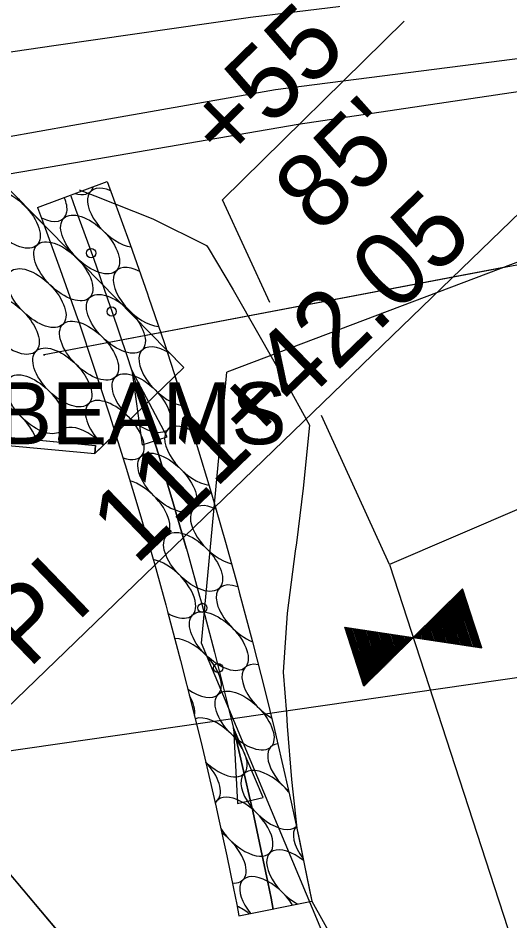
# Model space of a CAD drawing. Extents: x 1660112 to 1662239, y 668919 to 671377.
# Drawn here: x 1661383 to 1661422.7, y 670205.1 to 670278 of the extents above; entities that cross this region are included whole.
import ezdxf

# ---------------------------------------------------------------- set-up
doc = ezdxf.new("R2010")
doc.units = 0
for name, color, linetype in [('R_Concrete', 7, 'Continuous'), ('R_Horz Alg', 7, 'Continuous'), ('R_Horz Alg Annot', 7, 'Continuous'), ('R_Proposed Const Limits_Cut', 7, 'Continuous'), ('R_Proposed Const Limits_Hand', 7, 'Continuous'), ('R_ROW', 7, 'Continuous'), ('R_ROW Annot', 7, 'Continuous'), ('R_Water', 7, 'Continuous'), ('R_Water Annot', 7, 'Continuous'), ('S_BASELINE', 7, 'Continuous'), ('S_FENCE', 7, 'Continuous'), ('S_MSC_PT_SYM', 7, 'Continuous'), ('S_STREAM', 7, 'Continuous'), ('S_SURVEY_TEXT_ANNOT', 7, 'Continuous')]:
    doc.layers.add(name, color=color, linetype=linetype)

msp = doc.modelspace()

# ---------------------------------------------------------------- linework, layer by layer
at = {"layer": 'R_Concrete'}
for p, q in [((1661360.775, 670246.186), (1661389.245, 670243.511)), ((1661360.775, 670246.186), (1661389.245, 670243.511)), ((1661360.725, 670245.521), (1661389.183, 670242.848)), ((1661360.725, 670245.521), (1661389.183, 670242.848)), ((1661389.183, 670242.848), (1661389.245, 670243.511)), ((1661389.183, 670242.848), (1661389.245, 670243.511))]:
    msp.add_line(p, q, dxfattribs=at)
at = {"layer": 'R_Horz Alg'}
msp.add_arc((1655846.994, 664877.91), 7639.437, 42.561815, 45.4300379, dxfattribs=at)
at = {"layer": 'R_Horz Alg Annot'}
msp.add_lwpolyline([(1661344.445, 670185.981), (1661430.771, 670269.334)], dxfattribs=at)
at = {"layer": 'R_Proposed Const Limits_Cut'}
msp.add_line((1661397.789, 670227.54), (1661399.846, 670249.439), dxfattribs=at)
for points in [[(1661343.395, 670328.65), (1661484.178, 670303.544), (1661489.924, 670283.525), (1661399.846, 670249.439)], [(1661407.912, 670131.742), (1661429.38, 670152.079), (1661397.789, 670227.54)]]:
    msp.add_lwpolyline(points, dxfattribs=at)
at = {"layer": 'R_Proposed Const Limits_Hand'}
msp.add_line((1661406.708, 670206.706), (1661451.037, 670128.131), dxfattribs=at)
msp.add_lwpolyline([(1661387.926, 670264.146), (1661389.193, 670263.651), (1661393.882, 670261.815), (1661398.201, 670259.66), (1661398.328, 670259.454), (1661400.352, 670256.071), (1661402.442, 670252.447), (1661404.421, 670248.948), (1661404.5, 670248.807), (1661406.524, 670245.15), (1661406.004, 670240.056), (1661405.464, 670235.662), (1661405.378, 670234.982), (1661404.709, 670229.965), (1661404.396, 670225.211), (1661404.659, 670221.857), (1661404.731, 670220.85), (1661405.08, 670216.54), (1661405.188, 670215.557), (1661405.492, 670212.599), (1661406.708, 670206.706)], dxfattribs=at)
at = {"layer": 'R_ROW'}
msp.add_lwpolyline([(1661492.291, 670317.34), (1661506.22, 670273.906), (1661412.985, 670233.905), (1661445.828, 670132.902)], dxfattribs=at)
at = {"layer": 'R_ROW Annot'}
for points in [[(1661403.306, 670255.05), (1661399.509, 670263.348), (1661414.156, 670277.771)], [(1661412.985, 670233.905), (1661407.48, 670245.931)]]:
    msp.add_lwpolyline(points, dxfattribs=at)
at = {"layer": 'R_Water'}
for p, q in [((1661384.57, 670262.73), (1661390.195, 670264.818)), ((1661384.57, 670262.73), (1661390.195, 670264.818)), ((1661392.168, 670249.581), (1661393.019, 670243.548)), ((1661395.031, 670244.203), (1661392.168, 670249.581)), ((1661393.019, 670243.548), (1661395.031, 670244.203)), ((1661400.398, 670220.7), (1661400.71, 670214.616)), ((1661402.773, 670215.09), (1661400.398, 670220.7)), ((1661400.71, 670214.616), (1661402.773, 670215.09)), ((1661400.822, 670205.542), (1661406.708, 670206.706)), ((1661400.822, 670205.542), (1661406.708, 670206.706))]:
    msp.add_line(p, q, dxfattribs=at)
for points in [[(1661390.195, 670264.818), (1661390.6, 670263.727), (1661392.05, 670259.735), (1661393.45, 670255.742), (1661393.534, 670255.496), (1661394.807, 670251.73), (1661396.112, 670247.724), (1661397.319, 670243.877), (1661397.372, 670243.707), (1661398.578, 670239.704), (1661399.739, 670235.694), (1661400.703, 670232.227), (1661400.854, 670231.673), (1661401.917, 670227.668), (1661402.934, 670223.658), (1661403.683, 670220.576), (1661403.906, 670219.638), (1661404.826, 670215.641), (1661405.036, 670214.699), (1661405.703, 670211.626), (1661406.263, 670208.93), (1661406.528, 670207.614), (1661406.708, 670206.706)], [(1661390.195, 670264.818), (1661390.6, 670263.727), (1661392.05, 670259.735), (1661393.45, 670255.742), (1661393.534, 670255.496), (1661394.807, 670251.73), (1661396.112, 670247.724), (1661397.319, 670243.877), (1661397.372, 670243.707), (1661398.578, 670239.704), (1661399.739, 670235.694), (1661400.703, 670232.227), (1661400.854, 670231.673), (1661401.917, 670227.668), (1661402.934, 670223.658), (1661403.683, 670220.576), (1661403.906, 670219.638), (1661404.826, 670215.641), (1661405.036, 670214.699), (1661405.703, 670211.626), (1661406.263, 670208.93), (1661406.528, 670207.614), (1661406.708, 670206.706)], [(1661387.236, 670263.673), (1661387.637, 670262.592), (1661389.075, 670258.628), (1661390.465, 670254.66), (1661390.544, 670254.431), (1661391.807, 670250.69), (1661393.101, 670246.716), (1661394.299, 670242.893), (1661394.346, 670242.74), (1661395.544, 670238.763), (1661396.693, 670234.785), (1661397.65, 670231.342), (1661397.795, 670230.806), (1661398.85, 670226.827), (1661399.858, 670222.849), (1661400.6, 670219.791), (1661400.818, 670218.871), (1661401.732, 670214.895), (1661401.937, 670213.972), (1661402.598, 670210.921), (1661403.153, 670208.249), (1661403.414, 670206.948), (1661403.592, 670206.045)], [(1661384.57, 670262.73), (1661384.968, 670261.658), (1661386.399, 670257.719), (1661387.782, 670253.773), (1661387.855, 670253.56), (1661389.112, 670249.841), (1661390.397, 670245.897), (1661391.59, 670242.096), (1661391.632, 670241.959), (1661392.824, 670238.005), (1661393.966, 670234.056), (1661394.918, 670230.635), (1661395.059, 670230.116), (1661396.109, 670226.161), (1661397.111, 670222.211), (1661397.849, 670219.174), (1661398.063, 670218.273), (1661398.974, 670214.315), (1661399.176, 670213.41), (1661399.834, 670210.379), (1661400.385, 670207.728), (1661400.644, 670206.44), (1661400.822, 670205.542)], [(1661384.57, 670262.73), (1661384.968, 670261.658), (1661386.399, 670257.719), (1661387.782, 670253.773), (1661387.855, 670253.56), (1661389.112, 670249.841), (1661390.397, 670245.897), (1661391.59, 670242.096), (1661391.632, 670241.959), (1661392.824, 670238.005), (1661393.966, 670234.056), (1661394.918, 670230.635), (1661395.059, 670230.116), (1661396.109, 670226.161), (1661397.111, 670222.211), (1661397.849, 670219.174), (1661398.063, 670218.273), (1661398.974, 670214.315), (1661399.176, 670213.41), (1661399.834, 670210.379), (1661400.385, 670207.728), (1661400.644, 670206.44), (1661400.822, 670205.542)], [(1661396.562, 670235.24), (1661395.544, 670238.763), (1661394.346, 670242.74), (1661394.299, 670242.893), (1661393.101, 670246.716), (1661392.168, 670249.581)], [(1661395.658, 670249.116), (1661396.112, 670247.724), (1661397.319, 670243.877), (1661397.372, 670243.707), (1661398.578, 670239.704), (1661399.739, 670235.694), (1661400.703, 670232.227), (1661400.854, 670231.673), (1661401.917, 670227.668), (1661402.934, 670223.658), (1661403.683, 670220.576), (1661403.906, 670219.638), (1661404.826, 670215.641), (1661405.036, 670214.699), (1661405.703, 670211.626), (1661406.263, 670208.93), (1661406.528, 670207.614), (1661406.708, 670206.706)], [(1661396.572, 670235.204), (1661396.562, 670235.24)], [(1661403.592, 670206.045), (1661403.414, 670206.948), (1661403.153, 670208.249), (1661402.598, 670210.921), (1661401.937, 670213.972), (1661401.732, 670214.895), (1661400.818, 670218.871), (1661400.6, 670219.791), (1661400.38, 670220.696)]]:
    msp.add_lwpolyline(points, dxfattribs=at)
for centre in [(1661388.886, 670259.043), (1661390.545, 670254.317), (1661397.868, 670230.391), (1661399.138, 670225.545)]:
    msp.add_circle(centre, 0.375, dxfattribs=at)
at = {"layer": 'R_Water Annot'}
msp.add_lwpolyline([(1661324.141, 670309.192), (1661324.685, 670308.806), (1661313.922, 670293.642), (1661360.775, 670246.186), (1661389.245, 670243.511), (1661389.183, 670242.848), (1661396.368, 670249.803), (1661331.242, 670316.233)], close=True, dxfattribs=at)
for points in [[(1661385.099, 670261.298), (1661331.242, 670316.233), (1661324.141, 670309.192), (1661324.685, 670308.806), (1661313.922, 670293.642), (1661360.775, 670246.186), (1661389.245, 670243.511), (1661389.183, 670242.848), (1661390.848, 670244.46)], [(1661385.099, 670261.298), (1661331.242, 670316.233), (1661324.141, 670309.192), (1661324.685, 670308.806), (1661313.922, 670293.642), (1661360.775, 670246.186), (1661389.245, 670243.511), (1661389.183, 670242.848), (1661390.848, 670244.46)], [(1661395.658, 670249.116), (1661396.368, 670249.803), (1661394.97, 670251.228)]]:
    msp.add_lwpolyline(points, dxfattribs=at)
for centre in [(1661382.4, 670261.815), (1661382.4, 670261.815), (1661388.807, 670259.736), (1661388.807, 670259.736), (1661386.643, 670257.572), (1661386.643, 670257.572), (1661384.479, 670255.408), (1661384.479, 670255.408), (1661382.315, 670253.244), (1661382.315, 670253.244), (1661390.886, 670253.329), (1661390.886, 670253.329), (1661388.722, 670251.165), (1661388.722, 670251.165), (1661386.558, 670249.002), (1661386.558, 670249.002), (1661384.394, 670246.838), (1661384.394, 670246.838), (1661392.964, 670246.923), (1661392.964, 670246.923), (1661395.043, 670240.516), (1661395.043, 670240.516), (1661397.122, 670234.11), (1661397.122, 670234.11), (1661399.201, 670227.704), (1661399.201, 670227.704), (1661401.28, 670221.297), (1661401.28, 670221.297)]:
    msp.add_ellipse(centre, major_axis=(2.121, -2.121), ratio=0.51, dxfattribs=at)
for centre, start_param, end_param in [((1661386.728, 670266.142), 5.546257, 6.460002), ((1661386.728, 670266.142), 5.546257, 6.460002), ((1661390.97, 670261.899), 2.254283, 5.687545), ((1661390.97, 670261.899), 2.254283, 5.687545), ((1661386.728, 670266.142), 0.176817, 0.27749), ((1661386.728, 670266.142), 0.176817, 0.27749), ((1661384.564, 670263.978), 4.477364, 4.908534), ((1661384.564, 670263.978), 4.477364, 4.908534), ((1661384.564, 670263.978), 0.351911, 0.90907), ((1661384.564, 670263.978), 0.351911, 0.90907), ((1661384.564, 670263.978), 5.31948, 6.635096), ((1661384.564, 670263.978), 5.31948, 6.635096), ((1661393.049, 670255.493), 2.140255, 5.756238), ((1661393.049, 670255.493), 2.140255, 5.756238), ((1661395.128, 670249.087), 1.988124, 5.76284), ((1661395.128, 670249.087), 1.988124, 5.76284), ((1661382.231, 670244.674), 0.793691, 4.385656), ((1661382.231, 670244.674), 0.793691, 4.385656), ((1661390.801, 670244.759), 0.182712, 4.786912), ((1661390.801, 670244.759), 0.182712, 4.786912), ((1661388.637, 670242.595), 1.49632, 3.714754), ((1661388.637, 670242.595), 1.49632, 3.714754), ((1661397.207, 670242.68), 2.102172, 5.706232), ((1661397.207, 670242.68), 2.102172, 5.706232), ((1661390.801, 670244.759), 5.462929, 6.465898), ((1661390.801, 670244.759), 5.462929, 6.465898), ((1661392.88, 670238.353), 0.591955, 2.409324), ((1661392.88, 670238.353), 0.591955, 2.409324), ((1661399.286, 670236.274), 2.178346, 5.588496), ((1661399.286, 670236.274), 2.178346, 5.588496), ((1661392.88, 670238.353), 5.382716, 6.87514), ((1661392.88, 670238.353), 5.382716, 6.87514), ((1661394.958, 670231.946), 0.561247, 2.504385), ((1661394.958, 670231.946), 0.561247, 2.504385), ((1661401.365, 670229.867), 2.308065, 5.417843), ((1661401.365, 670229.867), 2.308065, 5.417843), ((1661394.958, 670231.946), 5.246457, 6.844432), ((1661394.958, 670231.946), 5.246457, 6.844432), ((1661397.037, 670225.54), 0.003695, 2.668642), ((1661397.037, 670225.54), 0.003695, 2.668642), ((1661403.444, 670223.461), 2.501616, 5.18729), ((1661403.444, 670223.461), 2.501616, 5.18729), ((1661397.037, 670225.54), 5.041941, 6.28688), ((1661397.037, 670225.54), 5.041941, 6.28688), ((1661394.874, 670223.376), 0.32888, 1.081044), ((1661394.874, 670223.376), 0.32888, 1.081044), ((1661399.116, 670219.134), 0.231625, 2.911914), ((1661399.116, 670219.134), 0.231625, 2.911914), ((1661405.523, 670217.055), 2.761129, 4.889586), ((1661405.523, 670217.055), 2.761129, 4.889586), ((1661399.116, 670219.134), 4.760361, 6.514811), ((1661399.116, 670219.134), 4.760361, 6.514811), ((1661396.953, 670216.97), 0.028226, 1.52087), ((1661396.953, 670216.97), 0.028226, 1.52087), ((1661403.359, 670214.891), 1.36324, 6.264103), ((1661403.359, 670214.891), 1.36324, 6.264103), ((1661401.195, 670212.727), 0.140772, 3.331922), ((1661401.195, 670212.727), 0.140772, 3.331922), ((1661396.953, 670216.97), 6.129944, 6.311412), ((1661396.953, 670216.97), 6.129944, 6.311412), ((1661401.195, 670212.727), 4.301186, 6.423957), ((1661401.195, 670212.727), 4.301186, 6.423957), ((1661399.031, 670210.563), 0.179416, 1.873074), ((1661399.031, 670210.563), 0.179416, 1.873074), ((1661407.602, 670210.648), 3.16115, 4.451881), ((1661407.602, 670210.648), 3.16115, 4.451881), ((1661405.438, 670208.485), 1.785875, 5.240078), ((1661405.438, 670208.485), 1.785875, 5.240078), ((1661399.031, 670210.563), 5.740441, 6.462601), ((1661399.031, 670210.563), 5.740441, 6.462601), ((1661403.274, 670206.321), 1.132132, 4.492736), ((1661403.274, 670206.321), 1.132132, 4.492736), ((1661401.11, 670204.157), 1.808761, 2.228277), ((1661401.11, 670204.157), 1.808761, 2.228277)]:
    msp.add_ellipse(centre, major_axis=(2.121, -2.121), ratio=0.51, start_param=start_param, end_param=end_param, dxfattribs=at)
at = {"layer": 'S_BASELINE'}
msp.add_line((1661335.191, 670212.073), (1662115.176, 670324.54), dxfattribs=at)
at = {"layer": 'S_FENCE'}
for p, q in [((1661446.198, 670262.441), (1661385.099, 670250.822)), ((1661437.439, 670143.547), (1661353.953, 670242.566)), ((1661418.875, 670231.913), (1661420.417, 670227.171)), ((1661418.079, 670231.128), (1661419.312, 670227.338)), ((1661418.159, 670231.207), (1661419.422, 670227.321)), ((1661418.238, 670231.285), (1661419.533, 670227.304)), ((1661418.318, 670231.364), (1661419.643, 670227.288)), ((1661418.398, 670231.442), (1661419.754, 670227.271)), ((1661418.477, 670231.521), (1661419.864, 670227.254)), ((1661418.557, 670231.599), (1661419.975, 670227.238)), ((1661418.636, 670231.677), (1661420.085, 670227.221)), ((1661418.716, 670231.756), (1661420.196, 670227.205)), ((1661418.796, 670231.834), (1661420.307, 670227.188)), ((1661417.362, 670230.422), (1661418.317, 670227.487)), ((1661417.442, 670230.5), (1661418.427, 670227.471)), ((1661417.522, 670230.579), (1661418.538, 670227.454)), ((1661417.601, 670230.657), (1661418.648, 670227.437)), ((1661417.681, 670230.736), (1661418.759, 670227.421)), ((1661417.76, 670230.814), (1661418.869, 670227.404)), ((1661417.84, 670230.893), (1661418.98, 670227.387)), ((1661417.92, 670230.971), (1661419.09, 670227.371)), ((1661417.999, 670231.05), (1661419.201, 670227.354)), ((1661416.646, 670229.716), (1661417.321, 670227.637)), ((1661416.725, 670229.794), (1661417.432, 670227.62)), ((1661416.805, 670229.873), (1661417.543, 670227.604)), ((1661416.884, 670229.951), (1661417.653, 670227.587)), ((1661416.964, 670230.03), (1661417.764, 670227.57)), ((1661417.044, 670230.108), (1661417.874, 670227.554)), ((1661417.123, 670230.187), (1661417.985, 670227.537)), ((1661417.203, 670230.265), (1661418.095, 670227.52)), ((1661417.283, 670230.343), (1661418.206, 670227.504)), ((1661415.849, 670228.931), (1661416.216, 670227.803)), ((1661415.929, 670229.009), (1661416.326, 670227.786)), ((1661416.008, 670229.088), (1661416.437, 670227.77)), ((1661416.088, 670229.166), (1661416.548, 670227.753)), ((1661416.168, 670229.245), (1661416.658, 670227.737)), ((1661416.247, 670229.323), (1661416.769, 670227.72)), ((1661416.327, 670229.402), (1661416.879, 670227.703)), ((1661416.407, 670229.48), (1661416.99, 670227.687)), ((1661416.486, 670229.559), (1661417.1, 670227.67)), ((1661416.566, 670229.637), (1661417.211, 670227.653)), ((1661409.456, 670228.819), (1661410.98, 670224.133)), ((1661409.566, 670228.803), (1661411.059, 670224.211)), ((1661409.677, 670228.786), (1661411.139, 670224.289)), ((1661409.787, 670228.77), (1661411.219, 670224.368)), ((1661409.898, 670228.753), (1661411.298, 670224.446)), ((1661410.009, 670228.736), (1661411.378, 670224.525)), ((1661410.119, 670228.72), (1661411.458, 670224.603)), ((1661410.23, 670228.703), (1661411.537, 670224.682)), ((1661410.34, 670228.686), (1661411.617, 670224.76)), ((1661410.451, 670228.67), (1661411.697, 670224.839)), ((1661410.561, 670228.653), (1661411.776, 670224.917)), ((1661410.672, 670228.637), (1661411.856, 670224.996)), ((1661410.782, 670228.62), (1661411.935, 670225.074)), ((1661410.893, 670228.603), (1661412.015, 670225.153)), ((1661411.004, 670228.587), (1661412.095, 670225.231)), ((1661411.114, 670228.57), (1661412.174, 670225.31)), ((1661411.225, 670228.553), (1661412.254, 670225.388)), ((1661411.335, 670228.537), (1661412.334, 670225.467)), ((1661411.446, 670228.52), (1661412.413, 670225.545)), ((1661411.556, 670228.504), (1661412.493, 670225.623)), ((1661411.667, 670228.487), (1661412.573, 670225.702)), ((1661411.778, 670228.47), (1661412.652, 670225.78)), ((1661411.888, 670228.454), (1661412.732, 670225.859)), ((1661411.999, 670228.437), (1661412.811, 670225.937)), ((1661412.109, 670228.42), (1661412.891, 670226.016)), ((1661412.22, 670228.404), (1661412.971, 670226.094)), ((1661412.33, 670228.387), (1661413.05, 670226.173)), ((1661412.441, 670228.371), (1661413.13, 670226.251)), ((1661412.551, 670228.354), (1661413.21, 670226.33)), ((1661412.662, 670228.337), (1661413.289, 670226.408)), ((1661412.773, 670228.321), (1661413.369, 670226.487)), ((1661412.883, 670228.304), (1661413.449, 670226.565)), ((1661412.994, 670228.287), (1661413.528, 670226.644)), ((1661413.104, 670228.271), (1661413.608, 670226.722)), ((1661413.215, 670228.254), (1661413.687, 670226.801)), ((1661413.325, 670228.238), (1661413.767, 670226.879)), ((1661413.436, 670228.221), (1661413.847, 670226.958)), ((1661413.546, 670228.204), (1661413.926, 670227.036)), ((1661415.132, 670228.225), (1661415.221, 670227.953)), ((1661415.212, 670228.303), (1661415.331, 670227.936)), ((1661415.292, 670228.382), (1661415.442, 670227.919)), ((1661415.371, 670228.46), (1661415.553, 670227.903)), ((1661415.451, 670228.539), (1661415.663, 670227.886)), ((1661415.531, 670228.617), (1661415.774, 670227.87)), ((1661415.61, 670228.696), (1661415.884, 670227.853)), ((1661415.69, 670228.774), (1661415.995, 670227.836)), ((1661415.77, 670228.852), (1661416.105, 670227.82)), ((1661413.657, 670228.188), (1661414.006, 670227.114)), ((1661413.768, 670228.171), (1661414.086, 670227.193)), ((1661413.878, 670228.154), (1661414.165, 670227.271)), ((1661413.989, 670228.138), (1661414.245, 670227.35)), ((1661414.099, 670228.121), (1661414.325, 670227.428)), ((1661414.21, 670228.105), (1661414.404, 670227.507)), ((1661414.32, 670228.088), (1661414.484, 670227.585)), ((1661414.431, 670228.071), (1661414.563, 670227.664)), ((1661414.542, 670228.055), (1661414.643, 670227.742)), ((1661414.652, 670228.038), (1661414.723, 670227.821)), ((1661414.763, 670228.021), (1661414.802, 670227.899)), ((1661414.873, 670228.005), (1661414.882, 670227.978)), ((1661414.973, 670228.068), (1661415, 670227.986)), ((1661415.053, 670228.146), (1661415.11, 670227.969))]:
    msp.add_line(p, q, dxfattribs=at)
for points in [[(1661422.623, 670257.958), (1661385.099, 670250.822)], [(1661422.623, 670257.958), (1661385.099, 670250.822)], [(1661393.975, 670195.099), (1661381.084, 670210.388)], [(1661393.975, 670195.099), (1661381.084, 670210.388)]]:
    msp.add_lwpolyline(points, dxfattribs=at)
for points in [[(1661418.887, 670231.924), (1661414.905, 670228), (1661420.433, 670227.169)], [(1661409.377, 670228.832), (1661414.905, 670228), (1661410.923, 670224.077)]]:
    msp.add_lwpolyline(points, close=True, dxfattribs=at)
at = {"layer": 'S_MSC_PT_SYM'}
msp.add_lwpolyline([(1661385.099, 670250.822), (1661385.099, 670250.872), (1661385.099, 670250.822), (1661385.049, 670250.822), (1661385.099, 670250.822), (1661385.099, 670250.772), (1661385.099, 670250.822), (1661385.149, 670250.822)], dxfattribs=at)
at = {"layer": 'S_STREAM'}
for points in [[(1661623.558, 670311.06), (1661600.758, 670306.674), (1661577.959, 670302.288), (1661555.159, 670297.902), (1661532.36, 670293.515), (1661508.209, 670288.486), (1661492.784, 670284.301), (1661477.359, 670280.116), (1661459.421, 670277.44), (1661441.483, 670274.763), (1661423.546, 670272.087), (1661405.608, 670269.41), (1661388.574, 670266.498), (1661371.539, 670263.586), (1661354.505, 670260.675), (1661337.471, 670257.763), (1661319.369, 670253.79), (1661298.791, 670248.535)], [(1661529.583, 670302.777), (1661515.84, 670298.832), (1661502.097, 670294.888), (1661488.354, 670290.944), (1661474.61, 670286.999), (1661456.395, 670284.767), (1661438.18, 670282.535), (1661419.964, 670280.302), (1661401.749, 670278.07), (1661386.076, 670275.795), (1661370.403, 670273.521)], [(1661531.195, 670294.623), (1661517.624, 670291.372), (1661504.053, 670288.121), (1661490.482, 670284.871), (1661476.911, 670281.62), (1661458.626, 670279.27), (1661440.341, 670276.919), (1661422.057, 670274.569), (1661403.772, 670272.218), (1661387.417, 670269.332), (1661371.062, 670266.445)]]:
    msp.add_lwpolyline(points, dxfattribs=at)

# ---------------------------------------------------------------- texts
at = {"layer": 'R_Horz Alg Annot'}
msp.add_text('PI  111+42.05', height=6, rotation=43.99593, dxfattribs=at).set_placement((1661383.83, 670225.4))
at = {"layer": 'R_ROW Annot'}
for s, p in [('+55', (1661400.001, 670265.879)), ("85'", (1661407.337, 670260.464))]:
    msp.add_text(s, height=6, rotation=44.32802, dxfattribs=at).set_placement(p)
at = {"layer": 'S_SURVEY_TEXT_ANNOT'}
msp.add_text('CONC DECK WOOD PIERS AND BEAMS', height=5, dxfattribs=at).set_placement((1661277.994, 670243.609))

doc.saveas('drawing.dxf')
